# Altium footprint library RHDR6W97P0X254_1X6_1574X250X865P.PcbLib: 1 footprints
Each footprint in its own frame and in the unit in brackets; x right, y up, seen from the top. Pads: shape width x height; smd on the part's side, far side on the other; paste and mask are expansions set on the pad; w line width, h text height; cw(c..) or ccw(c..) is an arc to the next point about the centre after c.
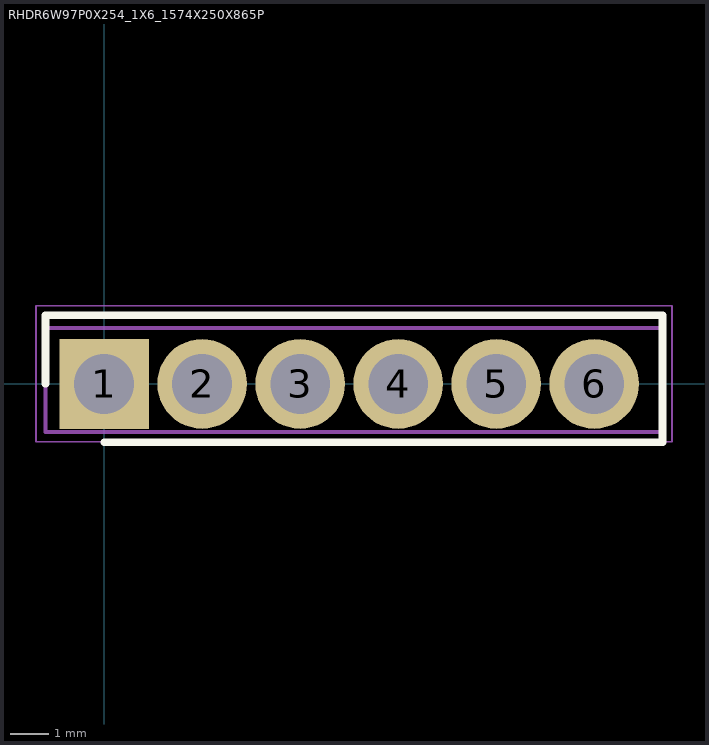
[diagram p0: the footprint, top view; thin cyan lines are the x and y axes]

## RHDR6W97P0X254_1X6_1574X250X865P [mm]
pads (6):
  rect 2.325x2.325 / inner round 2.325 / far side rect 2.325x2.325 hole 1.55: 1(0,0)
  round 2.325 hole 1.55: 2(2.54,0) 3(5.08,0) 4(7.62,0) 5(10.16,0) 6(12.7,0)
Top Overlay:
  lines w0.2: -1.52,0 -1.52,1.775 14.47,1.775 14.47,-1.512 0,-1.512
Mechanical 15:
  lines w0.1: -1.52,-1.25 -1.52,1.45 14.47,1.45 14.47,-1.25 -1.52,-1.25
Mechanical 20:
  lines w0.05: -1.77,-1.5 -1.77,2.025 14.72,2.025 14.72,-1.5 -1.77,-1.5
